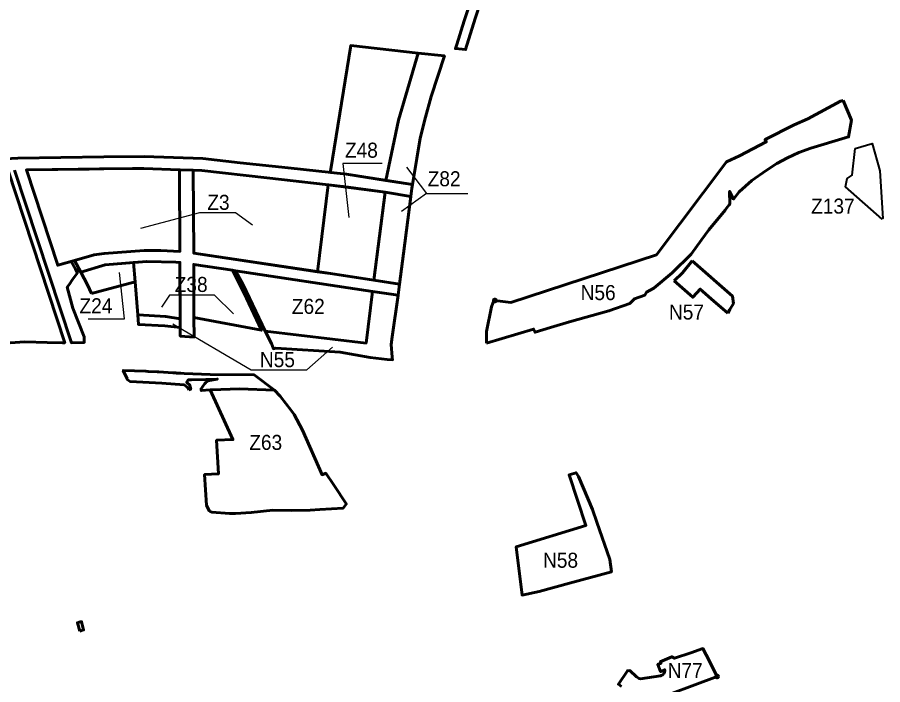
# Model space of a CAD drawing. Extents: x -650277 to -643425, y -1073980 to -1066720.
# Drawn here: x -647342 to -645961, y -1070373 to -1069308 of the extents above; entities that cross this region are included whole.
import ezdxf

# ---------------------------------------------------------------- set-up
doc = ezdxf.new("R2010")
doc.units = 0
doc.header["$LTSCALE"] = 9.6
doc.header["$PDMODE"] = 32
doc.header["$PDSIZE"] = 4.8
for name, color, linetype, lineweight in [('1', 7, 'Continuous', 60), ('13', 7, 'Continuous', 60), ('15', 7, 'Continuous', 60), ('18', 7, 'Continuous', 60), ('2', 7, 'Continuous', 40), ('42', 7, 'Continuous', 60), ('48', 7, 'Continuous', 60), ('59', 7, 'Continuous', 25), ('60', 7, 'Continuous', 60), ('63', 7, 'Continuous', 25), ('7', 7, 'Continuous', 60), ('9', 7, 'Continuous', 60)]:
    doc.layers.add(name, color=color, linetype=linetype, lineweight=lineweight)

msp = doc.modelspace()

# ---------------------------------------------------------------- linework, layer by layer
at = {"layer": '1'}
for points in [[(-647251.002, -1069695.852), (-647219.628, -1069686.746), (-647203.374, -1069684.716), (-647139.649, -1069679.961), (-647113.255, -1069679.966), (-647082.761, -1069681.399), (-647083.356, -1069551.018), (-647140.247, -1069549.071), (-647158.572, -1069549.252), (-647211.05, -1069549.77), (-647227.623, -1069550.23), (-647327.682, -1069551.263), (-647277.71, -1069703.421)], [(-646944.168, -1069563.743), (-647047.648, -1069552.245), (-647061.304, -1069551.773), (-647060.7, -1069683.894), (-646863, -1069714), (-646846, -1069575)], [(-647223.66, -1069748.26), (-647154.33, -1069729.69), (-647156.782, -1069698.901), (-647202.181, -1069702.678), (-647240.994, -1069714.513), (-647230.16, -1069734.42)], [(-647150.138, -1069782.334), (-647105.334, -1069785.168), (-647082.271, -1069788.81), (-647082.682, -1069698.791), (-647089.456, -1069698.579), (-647135.585, -1069697.137), (-647156.782, -1069698.901), (-647154.33, -1069729.69)], [(-647060.23, -1069786.932), (-646952.56, -1069807.13), (-646980.4, -1069746.98), (-646998.56, -1069711.443), (-647060.617, -1069702.116)]]:
    msp.add_lwpolyline(points, close=True, dxfattribs=at)
msp.add_lwpolyline([(-647369.3, -1069828.22), (-647330.46, -1069825.51), (-647294.38, -1069826.88), (-647270.09, -1069827.02), (-647266.581, -1069827.042), (-647356.899, -1069552.034)], dxfattribs=at)
at = {"layer": '13'}
msp.add_line((-646733.74, -1069471.688), (-646702.425, -1069364.771), dxfattribs=at)
msp.add_lwpolyline([(-646702.425, -1069364.771), (-646809.879, -1069353.002), (-646842.103, -1069553.182), (-646842.441, -1069555.283), (-646816.615, -1069558.064), (-646754.066, -1069567.993), (-646733.74, -1069471.688)], dxfattribs=at)
msp.add_lwpolyline([(-646842.148, -1069716.763), (-646772.906, -1069727.176), (-646755.269, -1069587.04), (-646846, -1069575), (-646862.955, -1069713.634)], close=True, dxfattribs=at)
at = {"layer": '15'}
for points in [[(-647346.554, -1069551.486), (-647256.034, -1069827.107), (-647235.49, -1069826.51), (-647235.62, -1069817.62), (-647253.45, -1069771.95), (-647262.46, -1069738.25), (-647259.11, -1069733.52), (-647253.97, -1069726.27), (-647246.42, -1069715.63), (-647249.555, -1069709.677), (-647256.061, -1069697.32), (-647277.71, -1069703.421), (-647327.682, -1069551.263), (-647204.208, -1069549.647), (-647140.247, -1069549.071), (-647083.356, -1069551.018), (-647061.304, -1069551.773), (-647047.702, -1069552.239), (-646944.167, -1069563.743), (-646822.169, -1069577.72), (-646755.269, -1069587.04), (-646714.037, -1069593.585), (-646712.34, -1069580.49), (-646711.444, -1069574.771), (-646711.442, -1069574.759), (-646816.615, -1069558.064), (-646910.029, -1069548.006), (-646986.633, -1069539.757), (-647046.325, -1069533.275), (-647140.008, -1069530.068), (-647204.293, -1069530.647), (-647341.697, -1069532.602), (-647434.969, -1069537.141)], [(-647083.356, -1069551.018), (-647082.761, -1069681.399), (-647113.255, -1069679.966), (-647139.649, -1069679.961), (-647203.374, -1069684.716), (-647219.628, -1069686.746), (-647251.002, -1069695.852), (-647240.994, -1069714.513), (-647202.181, -1069702.678), (-647135.585, -1069697.137), (-647089.456, -1069698.579), (-647082.682, -1069698.791), (-647082.206, -1069802.916)], [(-647060.617, -1069702.116), (-646998.56, -1069711.443), (-646993.771, -1069712.163), (-646775.286, -1069745.022), (-646734.48, -1069751.35), (-646732.143, -1069733.308), (-646772.906, -1069727.176), (-646842.148, -1069716.763), (-647060.7, -1069683.894), (-647061.304, -1069551.773), (-647083.356, -1069551.018)], [(-647082.206, -1069802.916), (-647082.145, -1069816.321), (-647060.029, -1069817.854), (-647060.23, -1069786.932), (-647060.617, -1069702.116)], [(-646931.67, -1069902.89), (-646964.111, -1069878.315), (-647034.195, -1069877.629), (-647076, -1069875.85), (-647081.25, -1069875.56), (-647081.26, -1069875.76), (-647088.94, -1069875.34), (-647088.93, -1069875.14), (-647094.24, -1069874.85), (-647116.31, -1069873.65), (-647118.77, -1069873.51), (-647133.58, -1069872.73), (-647136.94, -1069872.55), (-647173.23, -1069871.09), (-647167.14, -1069884.85)], [(-647167.14, -1069884.85), (-647166.8, -1069885.63), (-647163.55, -1069887.98), (-647162.03, -1069888.89), (-647111.76, -1069891.77)], [(-647111.76, -1069891.77), (-647075.97, -1069894.33), (-647071, -1069897.87), (-647068.2, -1069902.28)], [(-647068.2, -1069902.28), (-647065.47, -1069901.09), (-647067.02, -1069894.68), (-647071.73, -1069890.39), (-647070.87, -1069888.71), (-647069.57, -1069886.35), (-647064.32, -1069886.23), (-647041.25, -1069885.62), (-647035.6, -1069885.43), (-647023.04, -1069885), (-647035.53, -1069887.44), (-647037.79, -1069887.88), (-647041.47, -1069890.42), (-647042.75, -1069892.14), (-647046.49, -1069897.19), (-647048.8, -1069900.51), (-647048.67, -1069903.32), (-647034.51, -1069902.21)], [(-647034.51, -1069902.21), (-647032.16, -1069902.13), (-646987.56, -1069900.52), (-646931.67, -1069902.89)]]:
    msp.add_lwpolyline(points, dxfattribs=at)
msp.add_lwpolyline([(-647242.698, -1070287.238), (-647236.567, -1070285.154), (-647239.781, -1070272.031), (-647242.06, -1070272.35), (-647246.28, -1070273.733)], close=True, dxfattribs=at)
at = {"layer": '18'}
msp.add_lwpolyline([(-646785.437, -1069827.534), (-646775.286, -1069745.022), (-646993.771, -1069712.163), (-646981.92, -1069734.86), (-646946.369, -1069808.291)], close=True, dxfattribs=at)
at = {"layer": '2'}
for points in [[(-646004.7, -1069517.16), (-645977.73, -1069509.11), (-645965.36, -1069552.99), (-645960.78, -1069628.91), (-645961.36, -1069630.05)], [(-646017.39, -1069564.94), (-646017.39, -1069564.94), (-646009.52, -1069559.6), (-646004.7, -1069517.16)], [(-645961.36, -1069630.05), (-646020.4, -1069578.04), (-646017.39, -1069564.94)]]:
    msp.add_lwpolyline(points, dxfattribs=at)
at = {"layer": '42'}
msp.add_line((-646230.3, -1069760.5), (-646208.135, -1069779.937), dxfattribs=at)
for points in [[(-646023.96, -1069440.34), (-646028.16, -1069441.58), (-646080.35, -1069469.89), (-646102.15, -1069479.49), (-646148.5, -1069503), (-646146.8, -1069506.6), (-646189.17, -1069528.74), (-646209.9, -1069538.5), (-646321.973, -1069686.855), (-646554.262, -1069762.602), (-646579.873, -1069759.61)], [(-646017.63, -1069499.08), (-646017.63, -1069499.08), (-646015.16, -1069498.74), (-646010.65, -1069471.91), (-646023.96, -1069440.34)], [(-646491.18, -1069802.78), (-646491.18, -1069802.78), (-646460.97, -1069793.56), (-646397.74, -1069776.29), (-646364.67, -1069764.23), (-646357, -1069756.7), (-646340.48, -1069750.92), (-646337.97, -1069746.4), (-646325.92, -1069740.05), (-646296.64, -1069715.72), (-646266.27, -1069685.75), (-646250, -1069663.09), (-646238.19, -1069646.63), (-646212.43, -1069615.33), (-646210.03, -1069612.42), (-646205.9, -1069607.17), (-646205, -1069606.03), (-646205.25, -1069585.67), (-646198.82, -1069597.83), (-646190.07, -1069586.48), (-646169.9, -1069568.04), (-646146.81, -1069551.97), (-646129.87, -1069541.19), (-646112.56, -1069531.78), (-646094.39, -1069523.34), (-646075.48, -1069516.38), (-646020.75, -1069500), (-646017.63, -1069499.08)], [(-646265.02, -1069696.43), (-646280.5, -1069715.27), (-646293.76, -1069728)], [(-646208.135, -1069779.937), (-646204.6, -1069773.78), (-646199.17, -1069764.33), (-646200.67, -1069752.88), (-646265.02, -1069696.43)], [(-646293.76, -1069728), (-646263.929, -1069754.309), (-646263.36, -1069753.69), (-646252.07, -1069741.41), (-646230.3, -1069760.5)], [(-646579.873, -1069759.61), (-646581.489, -1069759.421), (-646585.51, -1069769.57), (-646593.34, -1069808.99), (-646593.34, -1069827.68)], [(-647082.271, -1069788.81), (-647105.334, -1069785.168), (-647105.334, -1069785.168), (-647150.138, -1069782.334), (-647148.9, -1069797.88), (-647107.04, -1069799.84)], [(-647107.04, -1069799.84), (-647082.206, -1069802.916), (-647082.271, -1069788.81)], [(-646593.34, -1069827.68), (-646518.19, -1069805.27), (-646515.63, -1069810.24), (-646491.18, -1069802.78)]]:
    msp.add_lwpolyline(points, dxfattribs=at)
msp.add_lwpolyline([(-646775.286, -1069745.022), (-646785.437, -1069827.534), (-646946.369, -1069808.291), (-646936.6, -1069828.47), (-646933.39, -1069836.51), (-646929.67, -1069835.68), (-646826.63, -1069841.84), (-646778.74, -1069850.44), (-646751.8, -1069853.72), (-646743.31, -1069854.26), (-646743.7, -1069850.07), (-646745.56, -1069829.84), (-646743.85, -1069817.72), (-646734.48, -1069751.35)], close=True, dxfattribs=at)
msp.add_point((-646579.873, -1069759.61), dxfattribs=at)
at = {"layer": '48'}
msp.add_point((-646225.15, -1070359.46), dxfattribs=at)
at = {"layer": '60'}
for points in [[(-646681.5, -1069434.17), (-646660.526, -1069369.36), (-646702.425, -1069364.771), (-646733.74, -1069471.688), (-646754.066, -1069567.993), (-646711.442, -1069574.759)], [(-646711.442, -1069574.759), (-646704.68, -1069533.06), (-646699.07, -1069500.57), (-646690.51, -1069466.97), (-646681.5, -1069434.17)]]:
    msp.add_lwpolyline(points, dxfattribs=at)
msp.add_lwpolyline([(-646755.269, -1069587.04), (-646772.906, -1069727.176), (-646732.143, -1069733.308), (-646725.82, -1069684.5), (-646714.037, -1069593.585)], close=True, dxfattribs=at)
at = {"layer": '63'}
msp.add_line((-646689.194, -1069588.733), (-646622.86, -1069588.733), dxfattribs=at)
for points in [[(-646759.573, -1069540.98), (-646822.671, -1069540.98), (-646813, -1069627)], [(-646720.743, -1069546.645), (-646689.194, -1069588.733), (-646728.832, -1069617.87)], [(-647145, -1069644), (-647051, -1069619), (-646994, -1069619), (-646967, -1069639)], [(-647229, -1069789), (-647171, -1069789), (-647179, -1069715)], [(-646997, -1069781), (-647027.656, -1069750.914), (-647099.524, -1069750.914), (-647112, -1069770)], [(-647094, -1069797), (-646969, -1069870), (-646880, -1069870), (-646839, -1069834)]]:
    msp.add_lwpolyline(points, dxfattribs=at)
at = {"layer": '7'}
msp.add_lwpolyline([(-646613.6, -1069267.04), (-646627.59, -1069310.34), (-646628.66, -1069313.66), (-646640.715, -1069350.951), (-646642.89, -1069357.68), (-646626.774, -1069359.349), (-646611.107, -1069309.68), (-646577.878, -1069206.485)], dxfattribs=at)
at = {"layer": '9'}
msp.add_lwpolyline([(-647032.16, -1069902.13), (-647034.51, -1069902.21), (-646998.06, -1069981.49), (-647024.05, -1069982.48), (-647021.27, -1070036.28), (-647043.25, -1070037.29), (-647040.12, -1070086.11), (-647036.03, -1070094.96), (-647034.17, -1070096.49), (-647031.73, -1070097.21), (-647003.49, -1070099.66), (-646993.92, -1070099.49), (-646968.89, -1070098.02), (-646934.63, -1070094.24), (-646904.97, -1070094.52), (-646874.9, -1070094.1), (-646859.29, -1070093.1), (-646821.89, -1070090.7), (-646817.15, -1070084.76), (-646816.9, -1070084.45), (-646837.65, -1070053.22), (-646849.79, -1070035.17), (-646855.62, -1070037.66), (-646886.85, -1069966.26), (-646900.26, -1069941.64), (-646904.72, -1069935.84), (-646922.79, -1069912.31), (-646931.67, -1069902.89), (-646987.56, -1069900.52)], close=True, dxfattribs=at)
for points in [[(-646417.23, -1070113.25), (-646424.17, -1070093.21), (-646446.21, -1070040.55), (-646450.22, -1070034.31), (-646461.415, -1070037.991), (-646434.503, -1070118.512), (-646545.78, -1070152.41), (-646536.47, -1070229.65), (-646509.31, -1070224.11), (-646460.8, -1070210.57)], [(-646460.8, -1070210.57), (-646393.97, -1070192.69), (-646396.51, -1070173.06), (-646417.23, -1070113.25)], [(-646336.35, -1070400.9), (-646225.15, -1070359.46), (-646242.56, -1070325.1), (-646247.667, -1070315.004), (-646267.3, -1070321.61), (-646293.14, -1070330.3), (-646297.4, -1070328.01), (-646315.84, -1070336.13), (-646314.84, -1070338.41), (-646319.95, -1070340.42), (-646315.46, -1070351.67), (-646308.791, -1070348.855), (-646308.59, -1070350.22), (-646309.18, -1070352.77), (-646309.99, -1070354.58), (-646311.82, -1070356.89), (-646314.6, -1070358.05), (-646315.7, -1070358.27), (-646347.49, -1070363.01), (-646349.76, -1070362.69), (-646353.81, -1070360.18), (-646364.34, -1070350.19), (-646368.4, -1070350.41), (-646382.67, -1070371.94), (-646377.86, -1070375.71)]]:
    msp.add_lwpolyline(points, dxfattribs=at)

# ---------------------------------------------------------------- texts
at = {"layer": '59', "width": 0.95}
msp.add_text('Z137', height=24, dxfattribs=at).set_placement((-646075, -1069621))
at = {"layer": '63', "width": 0.95}
for s, p in [('Z48', (-646819.248, -1069531.795)), ('Z82', (-646687.198, -1069577.402)), ('Z3', (-647039, -1069615)), ('Z38', (-647091, -1069746)), ('N56', (-646443, -1069759)), ('Z24', (-647243, -1069780)), ('Z62', (-646904, -1069781)), ('N57', (-646302, -1069790)), ('N55', (-646955, -1069866)), ('Z63', (-646972, -1069998)), ('N58', (-646503, -1070186)), ('N77', (-646304, -1070362))]:
    msp.add_text(s, height=24, dxfattribs=at).set_placement(p)

doc.saveas('drawing.dxf')
